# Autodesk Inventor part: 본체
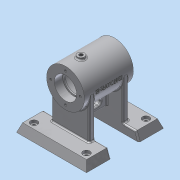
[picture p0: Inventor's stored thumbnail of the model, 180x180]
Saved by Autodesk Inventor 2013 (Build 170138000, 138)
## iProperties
Created: 2016-07
Part Number: 본체
Material: 알루미늄 6061
Document SubType Name: Modeling
Designer: dgall
Density: 1 g/cm^3
Author: dgall
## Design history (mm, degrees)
sketch "스케치1"
  geometry: L1 (0, 0)-(100, 0); L2 (100, 0)-(100, 110); L3 (100, 110)-(0, 110); L4 (0, 110)-(0, 0)
  constraints: 8 end point, 2 parallel, 1 horizontal, 1 perpendicular
  dimensions: "d0" = 100 distance of L2.end L3.end; "d2" = 110 distance of L1.end L2.end
extrude "돌출1" new body sketch "스케치1" distance "d3" = 12; taper "d4" = -20 deg
sketch "스케치2"
  geometry: L1 (75, 19.882)-(35, 19.882); L2 (35, 19.882)-(35, -12.264); L3 (35, -12.264)-(75, -12.264); L4 (75, -12.264)-(75, 19.882); L5 (110, 0)-(105.632, 12) reference; 1 further point
  constraints: 8 end point, 2 parallel, 1 horizontal, 1 perpendicular
  dimensions: "d5" = 35 distance from line of point (0, 0) L2; "d6" = 35 distance from line of L4 L5.start
extrude "돌출2" cut sketch "스케치2" stored distance "d7" = 12; taper "d8" = 0 deg
node "작업 평면1"
node "작업 평면2"
sketch "스케치4"
  geometry: L1 (20, 70)-(90, 70); L2 (90, 70)-(90, 97); L3 (90, 97)-(20, 97); L4 (20, 97)-(20, 70); L5 (20, 86)-(32, 86); L6 (32, 86)-(32, 84); L7 (32, 84)-(34, 84); L8 (34, 84)-(34, 92); L9 (34, 92)-(76, 92); L10 (76, 92)-(76, 84); L11 (76, 84)-(78, 84); L12 (78, 84)-(78, 86); L13 (78, 86)-(90, 86); L14 (35, 0)-(0, 0) reference; L15 (75, 0)-(75, 12) reference; L16 (35, 0)-(75, 0); 2 further points
  constraints: 28 end point, 8 parallel, 4 perpendicular, 2 collinear, 2 horizontal alignment, 2 midpoint, 2 point on line, 1 horizontal, 1 vertical alignment
  dimensions: "d11" = 54 diameter of L3 L1; "d13" = 32 diameter of L5 L1; "d14" = 28 diameter of L7 L1; "d15" = 44 diameter of L9 L1; "d16" = 12 distance of L5.start L5.end; "d17" = 42 distance of L8.end L9.end; "d18" = 12 distance of L12.end L13.end; "d19" = 70 distance between parallel lines of L14 L1; "d20" = 70 distance of L1.start L1.end
revolve "회전1" sketch "스케치4" stored, may be unused: angle "d21" = 90 deg
node "작업 평면3"
sketch "스케치5"
  geometry: L1 (-45.632, -58)-(45.632, -58) reference; L2 (-27, 0)-(-27, -58); L3 (27, 0)-(27, -58); L4 (-27, -58)-(27, -58); A1 r 27 centre (0, 0) between (-27, 0) and (27, 0) reference; 2 further points
  constraints: 6 end point, 2 perpendicular, 2 point on circle, 2 point on line, 2 tangent, 1 coincident, 1 collinear, 1 horizontal alignment, 2 other
extrude "돌출3" join sketch "스케치5" stored distance "d23" = 56; taper "d24" = 0 deg
extrude "돌출4" cut sketch "스케치5" stored distance "d25" = 40; taper "d26" = 0 deg
node "작업 평면4"
sketch "스케치6"
  geometry: L1 (35, 70)-(35, 12) reference; L2 (20, 43)-(90, 43) reference; L3 (75, 12)-(75, 70) reference; L4 (35, 22)-(75, 22); 1 further point
  constraints: 2 end point, 2 point on line, 1 perpendicular
  dimensions: "d28" = 21 distance between parallel lines of L4 L2
feature "리브1" sketch "스케치6" dims "d29" = 1, "d30" = 8, "d31" = 0, "d32" = 0, "d33" = 1, "d34" = 1
sketch "스케치7"
  geometry: L1 (21.298, 40)-(21.298, 0) reference; L2 (7.798, 12)-(7.798, 28); L3 (14.798, 12)-(14.798, 28); L4 (11.298, 12)-(11.298, 28); L5 (43.298, -35)-(43.298, 0) reference; A1 r 3.5 centre (11.298, 12) between (7.798, 12) and (14.798, 12); A2 r 3.5 centre (11.298, 28) between (14.798, 28) and (7.798, 28); 2 further points
  constraints: 6 end point, 4 point on circle, 2 centre point, 2 midpoint, 2 tangent, 2 vertical alignment, 1 equal radius, 1 horizontal alignment, 1 parallel
  dimensions: "d35" = 3.5 radius of A1; "d37" = 23 dimension on A2 A1; "d38" = 32 distance from line of point (11.298, 20) L5
extrude "돌출5" cut sketch "스케치7" distance "d39" = 40; taper "d40" = 0 deg
node "작업 평면5"
sketch "스케치8"
  geometry: L1 (-5, 26.533)-(-5, 30); L2 (-5, 30)-(0, 30); L3 (0, 30)-(0, 27); L4 (50, -70)-(-50, -70) reference; A1 r 27 centre (0, 0) between (-5, 26.533) and (0, 27) reference; A2 r 27 centre (0, 0) between (0, 27) and (-5, 26.533)
  constraints: 6 end point, 4 point on circle, 1 centre point, 1 coincident, 1 parallel, 1 perpendicular, 1 vertical, 1 vertical alignment
  dimensions: "d42" = 5 distance of L1.end L2.end; "d44" = 100 distance between parallel lines of L4 L2
revolve "회전2" sketch "스케치8" stored, may be unused: angle "d45" = 90 deg
sketch "스케치9"
  geometry: C1 r 5 at (0, 0) reference; 1 further point
hole "구멍1" sketch "스케치9" at (0, 0) diameter "d46" = 5.188; stored, may be unused: countersink angle "d50" = 90 deg, drill point angle "d52" = 0 deg; dims "d47" = 6, "d48" = 4, "d49" = 2, "d51" = 20
node "작업 평면6"
sketch "스케치10"
  geometry: L1 (-14.308, -22.897)-(-15.898, -25.441); L2 (-15.898, -25.441)-(-20.986, -22.262); L3 (-20.986, -22.262)-(-19.038, -19.145); L4 (0, 0)-(0, -27); C1 r 16 at (0, 0) reference; A1 r 27 centre (0, 0) between (-19.038, -19.145) and (0, -27) reference; A2 r 27 centre (0, 0) between (-19.038, -19.145) and (-14.308, -22.897); 1 further point
  constraints: 8 end point, 4 point on circle, 1 centre point, 1 coincident, 1 parallel, 1 perpendicular, 1 vertical
  dimensions: "d56" = 32 deg angle of L4 L1; "d57" = 6 distance of L1.end L2.end; "d58" = 30 distance from line of C1.centre L2; "d59" = 2.54414 vertical distance of L1.start L1.end
revolve "회전3" sketch "스케치10" stored, may be unused: angle "d60" = 90 deg
sketch "스케치11"
  geometry: C1 r 6 at (0, 0) reference; 1 further point
hole "구멍2" sketch "스케치11" at (0, 0) diameter "d61" = 5.188; stored, may be unused: countersink angle "d65" = 90 deg, drill point angle "d67" = 0 deg; dims "d62" = 6, "d63" = 4, "d64" = 2, "d66" = 20
fillet "모깎기1" dims "d68" = 0.3
fillet "모깎기2" dims "d69" = 3
sketch "스케치12"
  geometry: L1 (77, 35)-(77, 27) reference; L2 (77, 27)-(23, 27) reference; L3 (23, 27)-(23, 35) reference; L4 (23, 35)-(77, 35) reference; L5 (95.632, 35)-(4.368, 35) reference; L6 (4.368, 4.368)-(4.368, 35) reference; L7 (95.632, 4.368)-(4.368, 4.368) reference; L8 (95.632, 35)-(95.632, 4.368) reference; L9 (100, 0)-(100, 35) reference; 1 further point
fillet "모깎기3" dims "d70" = 2
fillet "모깎기4" dims "d71" = 2
fillet "모깎기5" dims "d72" = 2
sketch "스케치13"
  geometry: C1 r 16 at (0, 0) reference; A1 r 21 centre (0, 0) between (0, 21) and (-21, 0); 3 further points
  constraints: 4 point on circle, 1 centre point, 1 coincident
  dimensions: "d73" = 42 diameter of A1
hole "구멍3" sketch "스케치13" at (0, 21), (-21, 0), (0, -21), (21, 0) diameter "d74" = 3.242; stored, may be unused: countersink angle "d78" = 90 deg, drill point angle "d80" = 118 deg; dims "d75" = 8, "d76" = 4, "d77" = 2, "d79" = 10
node "작업 평면7"
sketch "스케치14"
  geometry: 1 further point
sketch "스케치15"
  geometry: L1 (0, 0)-(100, 0) reference; L2 (0, 35)-(0, 0) reference; L3 (100, 0)-(100, 35) reference; 2 further points
  dimensions: "d87" = 12.5 distance from line of L2 point (12.5, 12.5); "d88" = 12.5 distance from line of point (12.5, 12.5) L1; "d89" = 12.5 distance from line of L3 point (87.5, 12.5); "d90" = 12.5 distance from line of L1 point (87.5, 12.5)
hole "구멍4" sketch "스케치15" at (12.5, 12.5), (87.5, 12.5) diameter "d91" = 6; stored, may be unused: countersink angle "d95" = 90 deg, drill point angle "d97" = 118 deg; dims "d92" = 8, "d93" = 10, "d94" = 4, "d96" = 10
node "작업 평면8"
fillet "모깎기6" dims "d99" = 2
node "작업 평면9"
sketch "스케치16"
  geometry: L1 (-35, -27)-(-35, 27) reference; L2 (-35, 27)-(35, 27) reference; 2 further points
  constraints: 1 other
  dimensions: "d100" = 35 distance from line of L1 point (0, 0); "d101" = 27 distance from line of point (0, 0) L2
feature "엠보싱1" sketch "스케치16" dims "d11" = 54, "d13" = 32, "d14" = 28, "d15" = 44, "d16" = 12, "d17" = 42, "d18" = 12, "d19" = 70, "d20" = 70, "d102" = 0.5, "d103" = 0
node "솔리드1"
mirror "대칭1"
mirror "대칭2"
node "투영된 루프1"
other parameters: "d9" = 55, "d22" = -35, "d41" = -22, "d53" = -35, "d81" = 55, "d98" = -35
